// Mitsubishi GX Works2 project: 三菱Q系列CPU以太网通讯(TCP)   PLC: Q06UDEH

PROGRAM MAIN
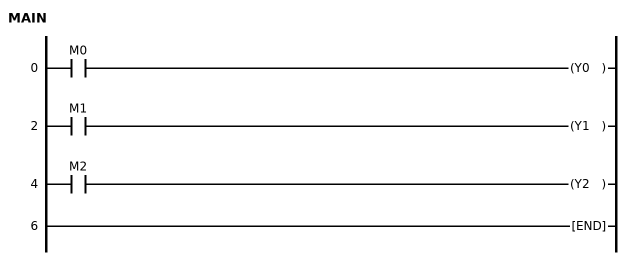
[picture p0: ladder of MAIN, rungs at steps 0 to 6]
0     LD      M0
      OUT     Y0
2     LD      M1
      OUT     Y1
4     LD      M2
      OUT     Y2
6     END
END_PROGRAM
